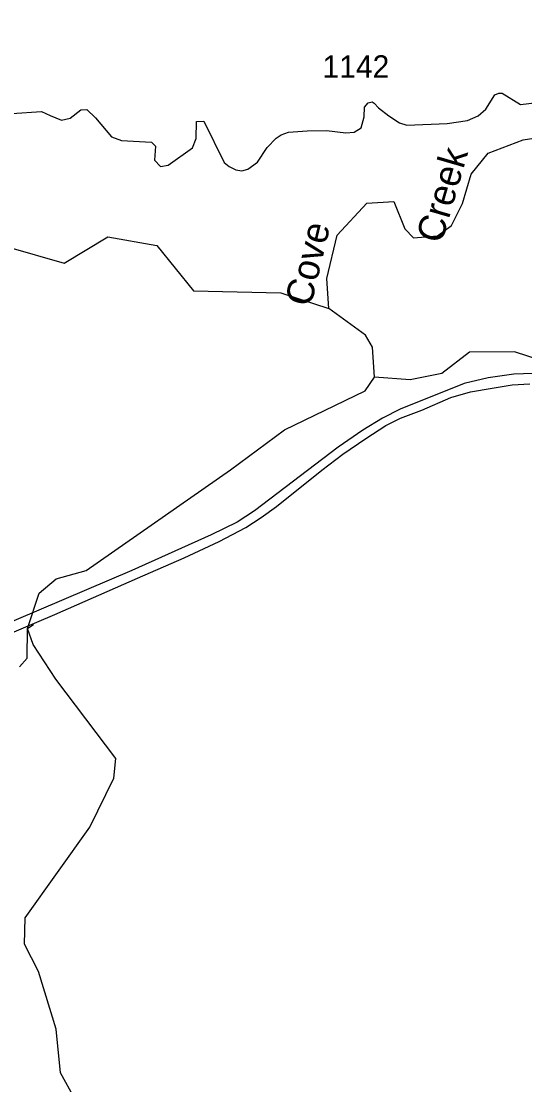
# Model space of a CAD drawing. Extents: x 990631 to 1056237, y 535999 to 585651.
# Drawn here: x 1014890 to 1017694, y 559461 to 565384 of the extents above; entities that cross this region are included whole.
import ezdxf

# ---------------------------------------------------------------- set-up
doc = ezdxf.new("R2010")
doc.units = 0
for name, color, linetype in [('Exist Hydrographic Creek Single Shore', 7, 'Continuous'), ('Exist Hydrographic Creek Single Shore Label', 7, 'Continuous'), ('Exist Road Primary Interstate Divided Center Attributed', 7, 'Continuous'), ('Exist Road Secondary Type 51 Attributed', 7, 'Continuous'), ('Exist Road Secondary Type 51 Number Label', 7, 'Continuous')]:
    doc.layers.add(name, color=color, linetype=linetype)

msp = doc.modelspace()

# ---------------------------------------------------------------- linework, layer by layer
at = {"layer": 'Exist Hydrographic Creek Single Shore'}
for points in [[(1016856.8, 563400.7), (1016845.8, 563568.3), (1016806.3, 563634.8), (1016602.8, 563783.3), (1016591.8, 563950.9), (1016649.8, 564192.6), (1016814.2, 564369.8), (1016964.5, 564379.9), (1017026.3, 564227.7), (1017074.5, 564177.5), (1017208.3, 564187.9), (1017285.3, 564245.4), (1017347.9, 564368.8), (1017395.1, 564532), (1017490.5, 564648.2), (1017684.8, 564723.1), (1018171.2, 564798.6), (1018349.9, 564909.9), (1018633.6, 565166.7), (1019099.5, 565383.8), (1019174.5, 565382.3)], [(1016856.8, 563400.7), (1016845.8, 563568.3), (1016806.3, 563634.8), (1016602.8, 563783.3), (1016591.8, 563950.9), (1016649.8, 564192.6), (1016814.2, 564369.8), (1016964.5, 564379.9), (1017026.3, 564227.7), (1017074.5, 564177.5), (1017208.3, 564187.9), (1017285.3, 564245.4), (1017347.9, 564368.8), (1017395.1, 564532), (1017490.5, 564648.2), (1017684.8, 564723.1), (1018171.2, 564798.6), (1018349.9, 564909.9), (1018633.6, 565166.7), (1019099.5, 565383.8), (1019174.5, 565382.3)], [(1011259.3, 563842.7), (1011570.5, 563813.5), (1011881.6, 563803.7), (1012251.2, 563657.8), (1012737.4, 563531.3), (1013204.1, 563745.4), (1013476.4, 563862.1), (1013616, 563902.9), (1013736.1, 563868.2), (1013836.2, 563823.2), (1013951.5, 563850.3), (1014035.6, 563895.9), (1014127.9, 564027.5), (1014390.5, 564144.3), (1014818.3, 564124.8), (1015129.5, 564037.3), (1015372.6, 564183.2), (1015644.9, 564134.6), (1015849.1, 563881.6), (1016335.3, 563871.9), (1016602.8, 563783.3)], [(1018259.1, 562223.7), (1018262.8, 562302.4), (1018520.7, 562536.8), (1018541.3, 562651.3), (1018489.8, 562862.4), (1018420.3, 563021.3), (1018180.1, 563321.5), (1018066, 563402.6), (1017637.1, 563542.6), (1017386.9, 563541), (1017232.8, 563422.7), (1017056.5, 563386.9), (1016856.8, 563400.7)], [(1018259.1, 562223.7), (1018262.8, 562302.4), (1018520.7, 562536.8), (1018541.3, 562651.3), (1018489.8, 562862.4), (1018420.3, 563021.3), (1018180.1, 563321.5), (1018066, 563402.6), (1017637.1, 563542.6), (1017386.9, 563541), (1017232.8, 563422.7), (1017056.5, 563386.9), (1016856.8, 563400.7)], [(1015252.1, 562323.8), (1016055.8, 562885.2), (1016355.2, 563108.9), (1016804.4, 563326.3), (1016856.8, 563400.7)], [(1015252.1, 562323.8), (1016055.8, 562885.2), (1016355.2, 563108.9), (1016804.4, 563326.3), (1016856.8, 563400.7)], [(1014924.7, 562002.2), (1014989.6, 562197.8), (1015083.9, 562277.9), (1015252.1, 562323.8)], [(1014924.7, 562002.2), (1014989.6, 562197.8), (1015083.9, 562277.9), (1015252.1, 562323.8)], [(1014879.7, 561787.4), (1014922.9, 561835.7), (1014924.7, 562002.2), (1014958.9, 562024.5)], [(1014879.7, 561787.4), (1014922.9, 561835.7), (1014924.7, 562002.2), (1014958.9, 562024.5)], [(1016571.4, 556616.2), (1016492.9, 556762.2), (1016494.5, 556811.4), (1016021.2, 557369), (1015966.6, 557488.3), (1015975.7, 558006.6), (1016003.6, 558354), (1015932.7, 558473.5), (1015777.9, 558578.4), (1015667.7, 558774.2), (1015191, 559233.5), (1015187.6, 559381.3), (1015109.1, 559527.2), (1015083.9, 559770.6), (1014986.1, 560090.9), (1014907.6, 560243.5), (1014912.8, 560391), (1015271.4, 560895.8), (1015405.6, 561168.8), (1015417.6, 561276.8), (1015082.1, 561720), (1014955.8, 561912.5), (1014924.7, 562002.2)], [(1016571.4, 556616.2), (1016492.9, 556762.2), (1016494.5, 556811.4), (1016021.2, 557369), (1015966.6, 557488.3), (1015975.7, 558006.6), (1016003.6, 558354), (1015932.7, 558473.5), (1015777.9, 558578.4), (1015667.7, 558774.2), (1015191, 559233.5), (1015187.6, 559381.3), (1015109.1, 559527.2), (1015083.9, 559770.6), (1014986.1, 560090.9), (1014907.6, 560243.5), (1014912.8, 560391), (1015271.4, 560895.8), (1015405.6, 561168.8), (1015417.6, 561276.8), (1015082.1, 561720), (1014955.8, 561912.5), (1014924.7, 562002.2)]]:
    msp.add_lwpolyline(points, dxfattribs=at)
at = {"layer": 'Exist Road Primary Interstate Divided Center Attributed'}
for points in [[(1017792.8, 563424.5), (1017632.1, 563417.8), (1017490.1, 563397.7), (1017356.1, 563365.5), (1016999.8, 563223.5), (1016902, 563173.9), (1016792.2, 563106.9), (1016654.2, 563011.7), (1016189.4, 562656.3), (1016091.7, 562594.7), (1015947, 562523.7), (1015506.3, 562324), (1014607.5, 561942.1)], [(1017792.8, 563424.5), (1017632.1, 563417.8), (1017490.1, 563397.7), (1017356.1, 563365.5), (1016999.8, 563223.5), (1016902, 563173.9), (1016792.2, 563106.9), (1016654.2, 563011.7), (1016189.4, 562656.3), (1016091.7, 562594.7), (1015947, 562523.7), (1015506.3, 562324), (1014607.5, 561942.1)], [(1014687.9, 561913.9), (1015077.7, 562080.1), (1015537.1, 562281.1), (1015797, 562395), (1015992.5, 562486.2), (1016141.2, 562563.9), (1016226.9, 562620.2), (1016311.3, 562681.8), (1016564.5, 562884.2), (1016681, 562972.9), (1016809.6, 563060), (1016919.5, 563132.3), (1017001.2, 563173.9), (1017120.4, 563216.8), (1017282.5, 563289.1), (1017392.3, 563319.9), (1017511.5, 563340), (1017622.7, 563358.8), (1017721.8, 563364.2)], [(1014687.9, 561913.9), (1015077.7, 562080.1), (1015537.1, 562281.1), (1015797, 562395), (1015992.5, 562486.2), (1016141.2, 562563.9), (1016226.9, 562620.2), (1016311.3, 562681.8), (1016564.5, 562884.2), (1016681, 562972.9), (1016809.6, 563060), (1016919.5, 563132.3), (1017001.2, 563173.9), (1017120.4, 563216.8), (1017282.5, 563289.1), (1017392.3, 563319.9), (1017511.5, 563340), (1017622.7, 563358.8), (1017721.8, 563364.2)]]:
    msp.add_lwpolyline(points, dxfattribs=at)
at = {"layer": 'Exist Road Secondary Type 51 Attributed'}
msp.add_lwpolyline([(1014837, 564870.9), (1015003, 564881.5), (1015050.4, 564859), (1015113.9, 564832.2), (1015161.6, 564843.9), (1015222, 564890.6), (1015255, 564892), (1015304.4, 564845.3), (1015392.3, 564739.5), (1015448.6, 564718.9), (1015616.1, 564710.6), (1015636.7, 564688.6), (1015632.6, 564610.3), (1015665.5, 564574.6), (1015708.1, 564581.5), (1015844, 564679), (1015864.6, 564729.9), (1015866, 564824.7), (1015907.2, 564827.4), (1016020.6, 564597.8), (1016048, 564574.9), (1016085.4, 564555.5), (1016119.1, 564550.4), (1016151.5, 564559.4), (1016204.9, 564599.7), (1016259.5, 564679.8), (1016309.4, 564732.3), (1016338, 564751.3), (1016378.5, 564765.9), (1016482.9, 564774.4), (1016589.2, 564775.8), (1016697.9, 564762.2), (1016744.7, 564765.2), (1016782.4, 564789.4), (1016799, 564851.3), (1016802, 564905.7), (1016821.6, 564929.8), (1016844.3, 564934.4), (1016854.8, 564928.3), (1016879, 564901.1), (1016936.3, 564857.3), (1016996.7, 564818.1), (1017037.5, 564804.5), (1017260.8, 564815.1), (1017375.5, 564831.7), (1017434.4, 564857.3), (1017476.7, 564893.6), (1017528, 564973.6), (1017549.1, 564984.2), (1017568.7, 564984.2), (1017669.9, 564920.8), (1017776.9, 564933.3)], dxfattribs=at)

# ---------------------------------------------------------------- texts
at = {"layer": 'Exist Hydrographic Creek Single Shore Label'}
for s, rotation, p in [('Creek', 73.84565, (1017230.4, 564140)), ('Creek', 73.84565, (1017230.4, 564140)), ('Cove', 76.52263, (1016502.4, 563788.7)), ('Cove', 76.52263, (1016502.4, 563788.7))]:
    msp.add_text(s, height=150, rotation=rotation, dxfattribs=at).set_placement(p)
at = {"layer": 'Exist Road Secondary Type 51 Number Label'}
msp.add_text('1142', height=125, dxfattribs=at).set_placement((1016567.7, 565069.2))

doc.saveas('drawing.dxf')
